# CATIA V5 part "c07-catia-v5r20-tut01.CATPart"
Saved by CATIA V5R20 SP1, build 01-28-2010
Part number: Part1
Bounding box of the stored display mesh (mm): x -150 to 150, y -150 to 150, z -127.513 to 0
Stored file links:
  D:\v5_r20\psrt_files_downloaded\c07-catia-v5r20-prt\c07-catia-v5r20-tut01.CATPart
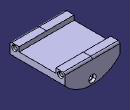
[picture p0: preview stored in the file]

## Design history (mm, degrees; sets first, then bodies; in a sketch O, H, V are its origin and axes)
Body1 (main body)
  Sketch1 on zx-plane, origin (0, 0, 0), H (-1, 0, 0), V (0, 0, 1)
    line L1 (0, 0) -> (150, 0)
    point P1 (150, 0)
    line L2 (150, 0) -> (150, -60)
    point P2 (150, -60)
    point P3 (-150, -60)
    point P4 (-150, 0)
    line L3 (-150, 0) -> (-150, -60)
    point P5 (0, 0)
    line L4 (0, 0) -> (-150, 0)
    arc A1 centre (0, 72.2876) radius 200 from (-150, -60) to (150, -60) ccw
    point P6 (0, 72.2876)
    distance L3 L2 = 300
    length L2 = 60
    radius A1 = 200
    horizontal: L1 H
    vertical: L2 V
    symmetry: P2 P3 V, P1 P4 V, L2 L3 V, O P5 V, L1 L4 V
    coincidence: P6 V, O P5
  Pad1: profile Sketch1, direction (0, 1, 0), length 150, mirrored extent
  Sketch2 on face of Pad1 from Sketch1.L3, origin (150, 0, 0), H (0, 1, 0), V (0, 0, 1)
    line L1 (-100, 0) -> (100, 0)
    reference projected line E1 (-150, 0) -> (150, 0) from edge [face of Pad1 from Sketch1.L3 | face of Pad1 from Sketch1.L4]
    line L2 (-100, 0) -> (-100, -25)
    line L3 (-100, -25) -> (100, -25)
    line L4 (100, 0) -> (100, -25)
    length L1 = 200
    distance L3 L1 = 25
    distance L4 V = 100
    coincidence: E1 L1
    vertical: L2 V, L4 V
    horizontal: L3 H
  Pocket1: profile Sketch2, direction (-1, 0, 0), through (limit type 3)
  Sketch3 on face of Pad1 from Sketch1.L3, origin (150, 95.7656, -28.4411), H (0, 1, 0), V (0, 0, 1)
    point P1 (29.2344, 8.4411)
    reference projected line E1 (-245.7656, 28.4411) -> (54.2344, 28.4411) from edge [face of Pad1 from Sketch1.L3 | face of Pad1 from Sketch1.L4]
    reference projected line E2 (54.2344, 28.4411) -> (54.2344, -31.5589) from edge [face of Pad1 from Sketch1.L3 | end face of Pad1]
    distance P1 E1 = 20
    distance P1 E2 = 25
  Hole1: placed by Sketch3, at (150, 125, -20) direction (-1, 0, 0), diameter 20, through (limit type 3), countersink depth 5, countersink angle 90
  Sketch4 on face of Pad1 from Sketch1.L3, origin (150, -127.9074, -34.2074), H (0, 1, 0), V (0, 0, 1)
    point P1 (2.9074, 14.2074)
    reference projected line E1 (-22.0926, 34.2074) -> (-22.0926, -25.7926) from edge [start face of Pad1 | face of Pad1 from Sketch1.L3]
    reference projected line E2 (-22.0926, 34.2074) -> (277.9074, 34.2074) from edge [face of Pad1 from Sketch1.L3 | face of Pad1 from Sketch1.L4]
    distance P1 E1 = 25
    distance P1 E2 = 20
  Hole2: placed by Sketch4, at (150, -125, -20) direction (-1, 0, 0), diameter 20, through (limit type 3), countersink depth 5, countersink angle 90
  Sketch5 on end face of Pad1, origin (-54.7231, 150, -53.7681), H (1, 0, 0), V (0, 0, -1)
    point P1 (54.7231, 46.2319)
    reference projected line E1 (54.7231, -53.7681) -> (204.7231, -53.7681) from edge [face of Pad1 from Sketch1.L4 | end face of Pad1]
    reference projected line E2 (-95.2769, 6.2319) -> (-95.2769, -53.7681) from edge [face of Pad1 from Sketch1.L2 | end face of Pad1]
    distance E1 P1 = 100
    distance E2 P1 = 150
  Hole3: placed by Sketch5, at (0, 150, -100) direction (0, -1, 0), diameter 30, through (limit type 3), counterbore diameter 40, counterbore depth 15
  Fillet1: radius 10, on edge [face of Pad1 from Sketch1.L1 | end face of Pad1]; edge [start face of Pad1 | face of Pad1 from Sketch1.L1]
